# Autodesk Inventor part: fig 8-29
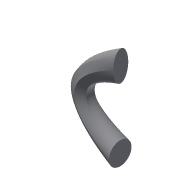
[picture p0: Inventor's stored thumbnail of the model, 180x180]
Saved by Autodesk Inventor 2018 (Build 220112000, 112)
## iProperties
Created: 2008-06
Part Number: fig 8-29
Document SubType Name: Modeling
Designer: CADCIM
Density: 1 g/cm^3
Material: Generic
Appearance: Default
Author: CADCIM
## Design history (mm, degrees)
sketch "Sketch1"
  geometry: L1 (-0.077, 5.773)-(4.961, 2.953); L2 (4.961, 2.953)-(5.038, -2.82); L3 (5.038, -2.82)-(0.077, -5.773); L4 (0.077, -5.773)-(-4.961, -2.953); L5 (-4.961, -2.953)-(-5.038, 2.82); L6 (-5.038, 2.82)-(-0.077, 5.773); 1 further point
  constraints: 12 end point, 13 other
  dimensions: "d0" = 10 distance between parallel lines of L2 L5
workplane "Work Plane1"
sketch "Sketch2"
  geometry: C1 r 7.5 at (-0.159, -25); 1 further point
  constraints: 1 centre point
  dimensions: "d2" = 15 diameter of C1; "d3" = 25 vertical distance of C1.centre point (0, 0)
sketch "Sketch3" dims "d4" = 10, "d5" = 5
  geometry: 2 further points; 1 other entity
  constraints: 2 other
  dimensions: "d6" = 25 vertical distance of point (0.175, 25) point (0, 0)
loft "Loft1" sketch "Sketch2", "Sketch3" dims "d7" = 0, "d8" = 90 deg, "d9" = 0, "d10" = 90 deg, "d11" = 0, "d12" = 90 deg
body "Solid1"
other parameters: "d1" = 25
